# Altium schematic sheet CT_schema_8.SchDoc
size 146 x 119 mm
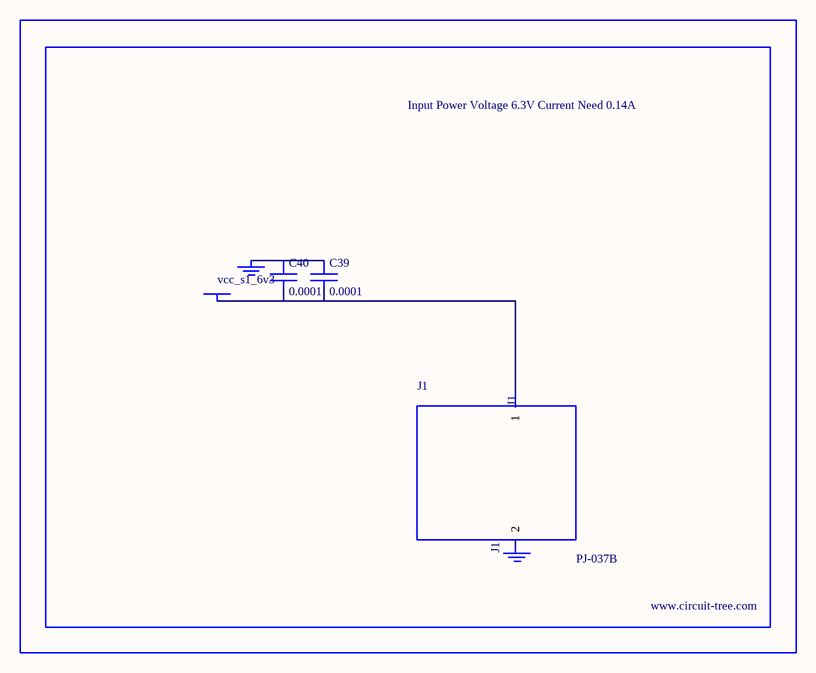
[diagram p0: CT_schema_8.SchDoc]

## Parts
BORDER7  (no value)
C39  0.0001  [EXV-9H]
C40  0.0001  [EXV-9H]
GND_INSTANCE_7_0  (no value)
GND_INSTANCE_7_1  (no value)
J1  PJ-037B  [PJ-037B_PACKAGE]
POWER_INSTANCE_7_0  vcc_s1_6v3

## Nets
NetC39_1: C39.1 C40.1 GND_INSTANCE_7_0.0(GND)
NetC39_2: C39.2 C40.2 J1.1 POWER_INSTANCE_7_0.0(PWR)

Not connected (* = marked no-connect by the designer): GND_INSTANCE_7_1 0(GND); J1 2

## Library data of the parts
BORDER7 = BORDER_PAGE7
C39 C40 = EDK107M035A9HAA
GND_INSTANCE_7_0 GND_INSTANCE_7_1 = GND
POWER_INSTANCE_7_0 = PWR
